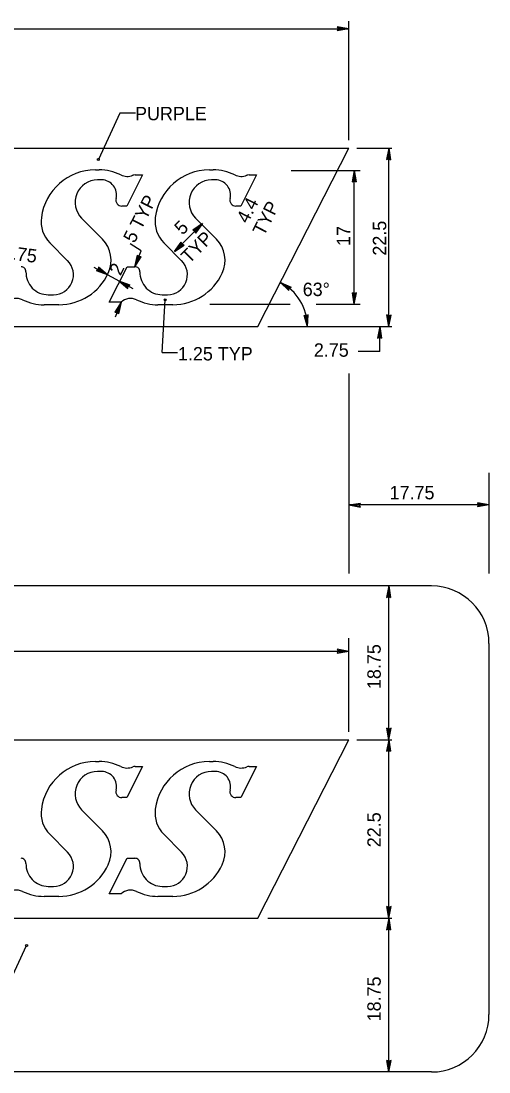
# Model space of a CAD drawing. Extents: x 10268197 to 10268739, y 2141503 to 2142677.
# Drawn here: x 10268711.9 to 10268736.3, y 2142368.9 to 2142423.7 of the extents above; entities that cross this region are included whole.
import ezdxf

# ---------------------------------------------------------------- set-up
doc = ezdxf.new("R2010")
doc.units = 0
for name, color, linetype in [('1', 7, 'Continuous'), ('21', 7, 'Continuous'), ('Default', 7, 'Continuous')]:
    doc.layers.add(name, color=color, linetype=linetype)

msp = doc.modelspace()

# ---------------------------------------------------------------- linework, layer by layer
at = {"layer": '1'}
for p, q in [((10268729.003, 2142417.529), (10268729.003, 2142423.746)), ((10268706.542, 2142423.333), (10268729.003, 2142423.333)), ((10268728.445, 2142423.343), (10268728.397, 2142423.236)), ((10268729.003, 2142423.333), (10268728.397, 2142423.236)), ((10268729.003, 2142423.333), (10268728.401, 2142423.449)), ((10268728.401, 2142423.449), (10268728.445, 2142423.343)), ((10268729.003, 2142423.333), (10268728.423, 2142423.292)), ((10268729.003, 2142423.333), (10268728.425, 2142423.393)), ((10268717.037, 2142418.929), (10268715.922, 2142416.522)), ((10268717.859, 2142418.929), (10268717.037, 2142418.929)), ((10268729.416, 2142417.115), (10268731.248, 2142417.115)), ((10268731.091, 2142417.115), (10268730.975, 2142416.513)), ((10268731.091, 2142417.115), (10268731.031, 2142416.536)), ((10268731.091, 2142407.798), (10268731.091, 2142417.115)), ((10268731.091, 2142417.115), (10268731.187, 2142416.509)), ((10268731.091, 2142417.115), (10268731.132, 2142416.535)), ((10268730.975, 2142416.513), (10268731.082, 2142416.557)), ((10268731.082, 2142416.557), (10268731.187, 2142416.509)), ((10268725.999, 2142415.95), (10268729.601, 2142415.95)), ((10268729.288, 2142415.95), (10268729.171, 2142415.349)), ((10268729.288, 2142415.95), (10268729.227, 2142415.372)), ((10268729.288, 2142408.963), (10268729.288, 2142415.95)), ((10268729.288, 2142415.95), (10268729.384, 2142415.345)), ((10268729.288, 2142415.95), (10268729.328, 2142415.371)), ((10268729.171, 2142415.349), (10268729.278, 2142415.393)), ((10268729.278, 2142415.393), (10268729.384, 2142415.345)), ((10268719.893, 2142411.713), (10268721.357, 2142413.177)), ((10268721.357, 2142413.177), (10268720.849, 2142412.834)), ((10268721.357, 2142413.177), (10268720.905, 2142412.811)), ((10268721.357, 2142413.177), (10268720.975, 2142412.739)), ((10268721.357, 2142413.177), (10268720.996, 2142412.681)), ((10268720.849, 2142412.834), (10268720.956, 2142412.79)), ((10268720.956, 2142412.79), (10268720.996, 2142412.681)), ((10268718.158, 2142411.75), (10268717.583, 2142412.117)), ((10268719.893, 2142411.713), (10268720.253, 2142412.209)), ((10268719.893, 2142411.713), (10268720.274, 2142412.151)), ((10268719.893, 2142411.713), (10268720.345, 2142412.079)), ((10268719.893, 2142411.713), (10268720.401, 2142412.056)), ((10268720.293, 2142412.101), (10268720.253, 2142412.209)), ((10268720.401, 2142412.056), (10268720.293, 2142412.101)), ((10268717.835, 2142410.926), (10268718.158, 2142411.75)), ((10268717.835, 2142410.926), (10268717.967, 2142411.525)), ((10268717.835, 2142410.926), (10268718.009, 2142411.481)), ((10268717.835, 2142410.926), (10268718.164, 2142411.444)), ((10268717.835, 2142410.926), (10268718.102, 2142411.443)), ((10268718.047, 2142411.442), (10268717.967, 2142411.525)), ((10268718.164, 2142411.444), (10268718.047, 2142411.442)), ((10268716.402, 2142410.507), (10268715.703, 2142410.889)), ((10268716.857, 2142410.26), (10268716.402, 2142410.507)), ((10268717.743, 2142409.776), (10268716.857, 2142410.26)), ((10268725.431, 2142410.105), (10268725.991, 2142409.855)), ((10268725.431, 2142410.105), (10268725.872, 2142409.679)), ((10268725.431, 2142410.105), (10268725.883, 2142409.739)), ((10268725.431, 2142410.105), (10268725.939, 2142409.823)), ((10268725.872, 2142409.679), (10268725.893, 2142409.793)), ((10268725.893, 2142409.793), (10268725.991, 2142409.855)), ((10268729.288, 2142408.963), (10268729.192, 2142409.568)), ((10268729.297, 2142409.52), (10268729.192, 2142409.568)), ((10268729.288, 2142408.963), (10268729.247, 2142409.543)), ((10268729.288, 2142408.963), (10268729.404, 2142409.565)), ((10268729.288, 2142408.963), (10268729.348, 2142409.542)), ((10268729.404, 2142409.565), (10268729.297, 2142409.52)), ((10268717.109, 2142409.068), (10268716.78, 2142408.55)), ((10268717.109, 2142409.068), (10268716.806, 2142408.297)), ((10268717.109, 2142409.068), (10268716.841, 2142408.551)), ((10268717.109, 2142409.068), (10268716.935, 2142408.513)), ((10268717.109, 2142409.068), (10268716.977, 2142408.469)), ((10268719.256, 2142406.438), (10268719.414, 2142409.191)), ((10268721.743, 2142408.963), (10268725.939, 2142408.963)), ((10268727.291, 2142408.963), (10268729.601, 2142408.963)), ((10268716.78, 2142408.55), (10268716.896, 2142408.552)), ((10268716.896, 2142408.552), (10268716.977, 2142408.469)), ((10268726.844, 2142407.798), (10268726.664, 2142408.386)), ((10268726.776, 2142408.353), (10268726.664, 2142408.386)), ((10268726.844, 2142407.798), (10268726.723, 2142408.367)), ((10268726.876, 2142408.411), (10268726.776, 2142408.353)), ((10268726.844, 2142407.798), (10268726.823, 2142408.38)), ((10268726.844, 2142407.798), (10268726.876, 2142408.411)), ((10268731.091, 2142407.798), (10268730.996, 2142408.404)), ((10268731.101, 2142408.356), (10268730.996, 2142408.404)), ((10268731.091, 2142407.798), (10268731.051, 2142408.378)), ((10268731.091, 2142407.798), (10268731.208, 2142408.401)), ((10268731.091, 2142407.798), (10268731.152, 2142408.378)), ((10268731.208, 2142408.401), (10268731.101, 2142408.356)), ((10268724.773, 2142407.798), (10268731.248, 2142407.798)), ((10268730.62, 2142407.798), (10268730.503, 2142407.197)), ((10268730.62, 2142407.798), (10268730.559, 2142407.22)), ((10268730.62, 2142406.505), (10268730.62, 2142407.798)), ((10268730.62, 2142407.798), (10268730.716, 2142407.194)), ((10268730.62, 2142407.798), (10268730.66, 2142407.219)), ((10268730.503, 2142407.197), (10268730.61, 2142407.242)), ((10268730.61, 2142407.242), (10268730.716, 2142407.194)), ((10268730.62, 2142406.505), (10268729.494, 2142406.505)), ((10268719.256, 2142406.438), (10268720.06, 2142406.438)), ((10268729.003, 2142405.351), (10268729.003, 2142394.918)), ((10268736.322, 2142400.16), (10268736.322, 2142394.918)), ((10268735.765, 2142398.498), (10268735.717, 2142398.392)), ((10268736.322, 2142398.489), (10268735.717, 2142398.392)), ((10268736.322, 2142398.489), (10268735.721, 2142398.605)), ((10268735.721, 2142398.605), (10268735.765, 2142398.498)), ((10268736.322, 2142398.489), (10268735.743, 2142398.448)), ((10268736.322, 2142398.489), (10268735.744, 2142398.549)), ((10268731.091, 2142394.266), (10268730.975, 2142393.664)), ((10268731.091, 2142394.266), (10268731.031, 2142393.687)), ((10268731.091, 2142386.239), (10268731.091, 2142394.266)), ((10268731.091, 2142394.266), (10268731.187, 2142393.66)), ((10268731.091, 2142394.266), (10268731.132, 2142393.686)), ((10268730.975, 2142393.664), (10268731.082, 2142393.708)), ((10268731.082, 2142393.708), (10268731.187, 2142393.66)), ((10268729.003, 2142386.654), (10268729.003, 2142391.546)), ((10268728.445, 2142390.852), (10268728.397, 2142390.745)), ((10268729.003, 2142390.842), (10268728.397, 2142390.745)), ((10268729.003, 2142390.842), (10268728.401, 2142390.958)), ((10268728.401, 2142390.958), (10268728.445, 2142390.852)), ((10268729.003, 2142390.842), (10268728.423, 2142390.801)), ((10268729.003, 2142390.842), (10268728.425, 2142390.902)), ((10268731.091, 2142386.239), (10268730.996, 2142386.845)), ((10268731.101, 2142386.797), (10268730.996, 2142386.845)), ((10268731.091, 2142386.239), (10268731.051, 2142386.819)), ((10268731.091, 2142386.239), (10268731.208, 2142386.841)), ((10268731.091, 2142386.239), (10268731.152, 2142386.818)), ((10268731.208, 2142386.841), (10268731.101, 2142386.797)), ((10268729.416, 2142386.239), (10268731.248, 2142386.239)), ((10268731.091, 2142386.239), (10268730.975, 2142385.638)), ((10268731.091, 2142386.239), (10268731.031, 2142385.661)), ((10268731.091, 2142376.923), (10268731.091, 2142386.239)), ((10268731.091, 2142386.239), (10268731.187, 2142385.634)), ((10268731.091, 2142386.239), (10268731.132, 2142385.66)), ((10268730.975, 2142385.638), (10268731.082, 2142385.682)), ((10268731.082, 2142385.682), (10268731.187, 2142385.634)), ((10268731.091, 2142376.923), (10268730.996, 2142377.529)), ((10268731.101, 2142377.481), (10268730.996, 2142377.529)), ((10268731.091, 2142376.923), (10268731.051, 2142377.503)), ((10268731.091, 2142376.923), (10268731.208, 2142377.525)), ((10268731.091, 2142376.923), (10268731.152, 2142377.502)), ((10268731.208, 2142377.525), (10268731.101, 2142377.481)), ((10268724.773, 2142376.923), (10268731.248, 2142376.923)), ((10268731.091, 2142376.923), (10268730.975, 2142376.322)), ((10268731.091, 2142376.923), (10268731.031, 2142376.345)), ((10268731.091, 2142368.897), (10268731.091, 2142376.923)), ((10268731.091, 2142376.923), (10268731.187, 2142376.318)), ((10268731.091, 2142376.923), (10268731.132, 2142376.344)), ((10268730.975, 2142376.322), (10268731.082, 2142376.366)), ((10268731.082, 2142376.366), (10268731.187, 2142376.318)), ((10268711.063, 2142373.086), (10268712.178, 2142375.493)), ((10268731.091, 2142368.897), (10268730.996, 2142369.502)), ((10268731.101, 2142369.454), (10268730.996, 2142369.502)), ((10268731.091, 2142368.897), (10268731.051, 2142369.477)), ((10268731.091, 2142368.897), (10268731.208, 2142369.499)), ((10268731.091, 2142368.897), (10268731.152, 2142369.476)), ((10268731.208, 2142369.499), (10268731.101, 2142369.454))]:
    msp.add_line(p, q, dxfattribs=at)
for centre in [(10268715.922, 2142416.522), (10268719.414, 2142409.191), (10268712.178, 2142375.493)]:
    msp.add_circle(centre, 0.0518, dxfattribs=at)
msp.add_arc((10268724.256, 2142407.799), 2.588, 0, 63.0012, dxfattribs=at)
at = {"layer": '21'}
for p, q in [((10268715.929, 2142410.898), (10268715.917, 2142410.783)), ((10268716.402, 2142410.507), (10268715.929, 2142410.898)), ((10268715.917, 2142410.783), (10268715.824, 2142410.713)), ((10268716.402, 2142410.507), (10268715.824, 2142410.713)), ((10268716.402, 2142410.507), (10268715.873, 2142410.75)), ((10268716.402, 2142410.507), (10268715.922, 2142410.838)), ((10268716.989, 2142410.184), (10268717.567, 2142409.978)), ((10268716.989, 2142410.184), (10268717.462, 2142409.793)), ((10268716.989, 2142410.184), (10268717.469, 2142409.853)), ((10268716.989, 2142410.184), (10268717.518, 2142409.942)), ((10268717.462, 2142409.793), (10268717.474, 2142409.908)), ((10268717.474, 2142409.908), (10268717.567, 2142409.978)), ((10268729.003, 2142398.489), (10268729.608, 2142398.585)), ((10268729.003, 2142398.489), (10268729.583, 2142398.529)), ((10268729.003, 2142398.489), (10268729.604, 2142398.372)), ((10268729.003, 2142398.489), (10268729.581, 2142398.428)), ((10268729.56, 2142398.479), (10268729.608, 2142398.585)), ((10268729.604, 2142398.372), (10268729.56, 2142398.479))]:
    msp.add_line(p, q, dxfattribs=at)
at = {"layer": 'Default'}
for p, q in [((10268699.479, 2142417.115), (10268729.003, 2142417.115)), ((10268724.257, 2142407.798), (10268729.003, 2142417.115)), ((10268715.767, 2142415.976), (10268715.963, 2142415.976)), ((10268721.719, 2142415.976), (10268721.915, 2142415.976)), ((10268716.094, 2142415.455), (10268715.872, 2142415.455)), ((10268718.229, 2142415.716), (10268717.407, 2142414.089)), ((10268717.841, 2142415.716), (10268718.229, 2142415.716)), ((10268722.046, 2142415.455), (10268721.824, 2142415.455)), ((10268724.181, 2142415.716), (10268723.358, 2142414.089)), ((10268723.793, 2142415.716), (10268724.181, 2142415.716)), ((10268717.407, 2142414.089), (10268717.148, 2142414.089)), ((10268723.358, 2142414.089), (10268723.099, 2142414.089)), ((10268715.049, 2142413.452), (10268716.134, 2142412.359)), ((10268721.001, 2142413.452), (10268722.086, 2142412.359)), ((10268714.318, 2142411.239), (10268713.387, 2142412.176)), ((10268720.269, 2142411.239), (10268719.338, 2142412.176)), ((10268716.48, 2142409.068), (10268717.42, 2142410.926)), ((10268717.42, 2142410.926), (10268717.835, 2142410.926)), ((10268713.307, 2142409.459), (10268713.586, 2142409.459)), ((10268719.259, 2142409.459), (10268719.538, 2142409.459)), ((10268713.864, 2142408.937), (10268713.086, 2142408.937)), ((10268717.109, 2142409.068), (10268716.48, 2142409.068)), ((10268719.816, 2142408.937), (10268719.037, 2142408.937)), ((10268698.615, 2142407.798), (10268724.257, 2142407.798)), ((10268736.322, 2142398.489), (10268729.003, 2142398.489)), ((10268733.322, 2142394.266), (10268672.322, 2142394.266)), ((10268736.322, 2142391.266), (10268736.322, 2142371.897)), ((10268729.003, 2142390.842), (10268676.642, 2142390.842)), ((10268699.479, 2142386.239), (10268729.003, 2142386.239)), ((10268724.257, 2142376.923), (10268729.003, 2142386.239)), ((10268715.767, 2142385.101), (10268715.963, 2142385.101)), ((10268721.719, 2142385.101), (10268721.915, 2142385.101)), ((10268716.094, 2142384.579), (10268715.872, 2142384.579)), ((10268718.229, 2142384.84), (10268717.407, 2142383.214)), ((10268717.841, 2142384.84), (10268718.229, 2142384.84)), ((10268722.046, 2142384.579), (10268721.824, 2142384.579)), ((10268724.181, 2142384.84), (10268723.358, 2142383.214)), ((10268723.793, 2142384.84), (10268724.181, 2142384.84)), ((10268717.407, 2142383.214), (10268717.148, 2142383.214)), ((10268723.358, 2142383.214), (10268723.099, 2142383.214)), ((10268715.049, 2142382.577), (10268716.134, 2142381.484)), ((10268721.001, 2142382.577), (10268722.086, 2142381.484)), ((10268714.318, 2142380.364), (10268713.387, 2142381.301)), ((10268720.269, 2142380.364), (10268719.338, 2142381.301)), ((10268716.48, 2142378.193), (10268717.42, 2142380.051)), ((10268717.42, 2142380.051), (10268717.835, 2142380.051)), ((10268713.307, 2142378.584), (10268713.586, 2142378.584)), ((10268719.259, 2142378.584), (10268719.538, 2142378.584)), ((10268713.864, 2142378.062), (10268713.086, 2142378.062)), ((10268717.109, 2142378.193), (10268716.48, 2142378.193)), ((10268719.816, 2142378.062), (10268719.037, 2142378.062)), ((10268698.615, 2142376.923), (10268724.257, 2142376.923)), ((10268733.322, 2142368.897), (10268672.322, 2142368.897))]:
    msp.add_line(p, q, dxfattribs=at)
for centre, start, end in [((10268733.322, 2142391.266), 0, 90), ((10268733.322, 2142371.897), 270, 0)]:
    msp.add_arc(centre, 3, start, end, dxfattribs=at)
for centre, major_axis, start_param, end_param in [((10268715.767, 2142413.109), (0, 2.868), 0, 1.436562), ((10268715.963, 2142413.369), (0, 2.607), 5.830963, 6.283185), ((10268721.718, 2142413.109), (0, 2.868), 0, 1.436562), ((10268721.915, 2142413.369), (0, 2.607), 5.830963, 6.283185), ((10268715.872, 2142414.282), (0, -1.173), 3.141593, 5.497787), ((10268716.095, 2142414.673), (0, -0.782), 1.321066, 3.141593), ((10268717.433, 2142416.418), (0, 0.782), 2.68937, 3.526171), ((10268717.841, 2142415.403), (0, 0.313), 0, 0.384579), ((10268721.824, 2142414.282), (0, -1.173), 3.141593, 5.497787), ((10268722.046, 2142414.673), (0, -0.782), 1.321066, 3.141593), ((10268723.385, 2142416.418), (0, 0.782), 2.68937, 3.526171), ((10268723.792, 2142415.403), (0, 0.313), 0, 0.384579), ((10268717.148, 2142414.402), (0, -0.313), 4.462658, 6.283185), ((10268723.099, 2142414.402), (0, -0.313), 4.462658, 6.283185), ((10268714.484, 2142413.283), (0, 1.564), 1.436562, 2.356194), ((10268720.436, 2142413.283), (0, 1.564), 1.436562, 2.356194), ((10268715.036, 2142411.253), (0, -1.564), 1.133591, 2.356194), ((10268720.988, 2142411.253), (0, -1.564), 1.133591, 2.356194), ((10268711.884, 2142410.665), (0, 0.261), 4.689114, 6.283185), ((10268713.586, 2142410.502), (0, -1.043), 0, 2.356194), ((10268717.836, 2142410.665), (0, 0.261), 4.689114, 6.283185), ((10268719.537, 2142410.502), (0, -1.043), 0, 2.356194), ((10268713.307, 2142410.632), (0, 1.173), 1.547521, 3.141593), ((10268713.864, 2142411.805), (0, -2.868), 0, 1.133591), ((10268719.258, 2142410.632), (0, 1.173), 1.547521, 3.141593), ((10268719.816, 2142411.805), (0, -2.868), 0, 1.133591), ((10268711.653, 2142408.536), (0, -0.73), 2.69443, 3.895387), ((10268717.605, 2142408.536), (0, -0.73), 2.69443, 3.895387), ((10268713.085, 2142411.545), (0, -2.607), 5.836023, 6.283185), ((10268719.037, 2142411.545), (0, -2.607), 5.836023, 6.283185), ((10268715.767, 2142382.233), (0, 2.868), 0, 1.436562), ((10268715.963, 2142382.494), (0, 2.607), 5.830963, 6.283185), ((10268721.718, 2142382.233), (0, 2.868), 0, 1.436562), ((10268721.915, 2142382.494), (0, 2.607), 5.830963, 6.283185), ((10268715.872, 2142383.407), (0, -1.173), 3.141593, 5.497787), ((10268716.095, 2142383.798), (0, -0.782), 1.321066, 3.141593), ((10268717.433, 2142385.542), (0, 0.782), 2.68937, 3.526171), ((10268717.841, 2142384.528), (0, 0.313), 0, 0.384579), ((10268721.824, 2142383.407), (0, -1.173), 3.141593, 5.497787), ((10268722.046, 2142383.798), (0, -0.782), 1.321066, 3.141593), ((10268723.385, 2142385.542), (0, 0.782), 2.68937, 3.526171), ((10268723.792, 2142384.528), (0, 0.313), 0, 0.384579), ((10268717.148, 2142383.527), (0, -0.313), 4.462658, 6.283185), ((10268723.099, 2142383.527), (0, -0.313), 4.462658, 6.283185), ((10268714.484, 2142382.408), (0, 1.564), 1.436562, 2.356194), ((10268720.436, 2142382.408), (0, 1.564), 1.436562, 2.356194), ((10268715.036, 2142380.378), (0, -1.564), 1.133591, 2.356194), ((10268720.988, 2142380.378), (0, -1.564), 1.133591, 2.356194), ((10268713.586, 2142379.626), (0, -1.043), 0, 2.356194), ((10268719.537, 2142379.626), (0, -1.043), 0, 2.356194), ((10268711.884, 2142379.79), (0, 0.261), 4.689114, 6.283185), ((10268713.307, 2142379.757), (0, 1.173), 1.547521, 3.141593), ((10268713.864, 2142380.93), (0, -2.868), 0, 1.133591), ((10268717.836, 2142379.79), (0, 0.261), 4.689114, 6.283185), ((10268719.258, 2142379.757), (0, 1.173), 1.547521, 3.141593), ((10268719.816, 2142380.93), (0, -2.868), 0, 1.133591), ((10268711.653, 2142377.66), (0, -0.73), 2.69443, 3.895387), ((10268713.085, 2142380.669), (0, -2.607), 5.836023, 6.283185), ((10268717.605, 2142377.66), (0, -0.73), 2.69443, 3.895387), ((10268719.037, 2142380.669), (0, -2.607), 5.836023, 6.283185)]:
    msp.add_ellipse(centre, major_axis=major_axis, ratio=0.992614, start_param=start_param, end_param=end_param, dxfattribs=at)

# ---------------------------------------------------------------- texts
at = {"layer": '1'}
for s, p in [('PURPLE', (10268717.839, 2142418.567)), ('63°', (10268726.596, 2142409.392)), ('1.25 TYP', (10268720.08, 2142406.031)), ('2.75', (10268727.176, 2142406.224)), ('17.75', (10268731.133, 2142398.783))]:
    msp.add_text(s, height=0.7, dxfattribs=at).set_placement(p)
for s, rotation, p in [('5 TYP', 62.9994, (10268717.808, 2142412.113)), ('4.4', 63, (10268723.722, 2142413.137)), ('TYP', 63, (10268724.569, 2142412.485)), ('5', 45, (10268720.314, 2142412.54)), ('22.5', 90, (10268730.956, 2142411.501)), ('TYP', 45, (10268720.667, 2142411.051)), ('17', 90, (10268729.075, 2142412.007)), ('3.75', 352.5994, (10268710.861, 2142411.355)), ('2', 63, (10268717.076, 2142410.414)), ('18.75', 90, (10268730.67, 2142388.881)), ('22.5', 90, (10268730.67, 2142380.626)), ('18.75', 90, (10268730.67, 2142371.539))]:
    msp.add_text(s, height=0.7, rotation=rotation, dxfattribs=at).set_placement(p)

doc.saveas('drawing.dxf')
